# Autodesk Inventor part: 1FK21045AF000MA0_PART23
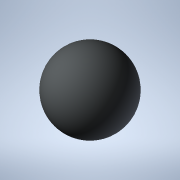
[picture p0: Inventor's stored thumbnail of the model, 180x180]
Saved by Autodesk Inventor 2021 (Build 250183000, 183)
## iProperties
Created: 2025-04
Part Number: 1FK21045AF000MA0_PART23
Material: Generic
Catalog Web Link: www.3dfindit.com
Description: -Servo synchronous motor
Document SubType Name: Modeling
Designer: psAdmin
Mass: 0.137258 g
Surface Area: 1.2868 cm^2
Volume: 0.137258 cm^3
Density: 1 g/cm^3
Appearance: PSOLRGB-212-217-219
Category: PARTsolutions
Title: 1FK21045AF000MA0_PART23
Author: Cadenas PARTsolutions
Comments: Servo synchronous motor
Sending System: PARTsolutions
Preprocessor: ST-DEVELOPER v19.3
PSOL_IDENT_0: {$CADENAS_DATA/23d-libs/siemens_ag/_cat_/8b/0a/1fk21045af000ma0.prj},216 {VTYP=3D},{NB=1FK21045AF000
PSOL_IDENT_1: MA0_PART23},{LINA=1FK21045AF000MA0_PART23},{NN=1FK21045AF000MA0_PART23},{NOPRJ=TRUE},{DATE=19.08.202
PSOL_IDENT_2: 5 14:00:48},{GEOMDATE=30.07.2025 02:00:28},{VERSION=},{LINEID=10},{WBVAR=},{WBNUMERIC=}  {NB=1FK2104
PSOL_IDENT_3: 5AF000MA0_PART23},{LINA=1FK21045AF000MA0_PART23},{KT=DUMMY},{PREVIEW=../../../_pool_/a9/69/p_d211_xx
PSOL_IDENT_4: _00818j.png},{DESCSHORT=SIMOTICS S-1FK2 HD, SINAMICS S210 3AC 400V-480V, 2.4 Nm, 3000 rpm},{DESCLONG=
PSOL_IDENT_5: SIMOTICS S-1FK2 HD servo motor M0=2.4 Nm; PN = 0.75 kW at nN=3000 rpm (380-480 V); PN = 0.375 kW at
PSOL_IDENT_6: nN=1500 rpm (200-240 V); degree of protection IP64; cylindrical shaft D19x40mm; absolute encoder 22-
PSOL_IDENT_7: bit + 12-bit multiturn (encoder AM22DQC); with OCC interface; plug size M17, rotatable; SIMOTICS S-1
PSOL_IDENT_8: FK2 servomotorfor a wide range of uses in industrial environments. SIMOTICS S‑1FK2 servomotors are c
PSOL_IDENT_9: ompact synchronous motors with a high dynamic performance that set themselves apart as a result of t
PSOL_IDENT_10: heir high power density, degree of protection and overload capability. The motors are available in t
PSOL_IDENT_11: wo variants: as High Dynamic variant (highest dynamic performance as a result of the low intrinsic m
PSOL_IDENT_12: oment of inertia for applications demanding a high dynamic performance with low moved masses) - and
PSOL_IDENT_13: as Compact variant (precise and stable closed-loop control for medium up to large moved masses as a
PSOL_IDENT_14: result of a medium intrinsic moment of inertia). SIMOTICSS‑1FK2 servomotors fully exploit their stre
PSOL_IDENT_15: ngths in a system with the SINAMICSS210 frequency converter and simple connection using the one cabl
PSOL_IDENT_16: e connection (OCC). Advantages include the short control and positioning times, fast and precise cor
PSOL_IDENT_17: rection of disturbing quantities as well as stable control with a high dynamic performance. The serv
PSOL_IDENT_18: o motors can be configured to address a wide range of requirements. For example with and without hol
PSOL_IDENT_19: ding brake, IP64 or IP65 degree of protection, singleturn or multiturn absolute encoders - to name j
PSOL_IDENT_20: ust a few. Further, the servomotors are available in different shaft heights extending from 20 to 10
PSOL_IDENT_21: 0. A shaft sealing ring is available to achieve an IP65 degree of protection and for subsequent moun
PSOL_IDENT_22: ting at the motor or as spare part. SIMOTICS - the optimum motor for each and every motion control a
PSOL_IDENT_23: pplication.},{INTNO=195125050112},{SUPPLIERALTNO=1FK2104-5AF00-0MA0},{MANUID=1FK21045AF000MA0},{MANU
PSOL_IDENT_24: NAME=Siemens},{MANUTYPEDESC=Synchronous motor 1FK2-HD 2.4 NM},{AAU732=SIMOTICS},{AAO057=S-1FK2},{AAU
PSOL_IDENT_25: 734=SIMOTICS S-1FK2 HD servo motor M0=2.4 Nm; PN = 0.75 kW at nN=3000 rpm (380-480 V); PN = 0.375 kW
PSOL_IDENT_26: at nN=1500 rpm (200-240 V); degree of protection IP64; cylindrical shaft D19x40mm; absolute encoder
PSOL_IDENT_27: 22-bit + 12-bit multiturn (encoder AM22DQC); with OCC interface; plug size M17, rotatable;},{AAW338=
PSOL_IDENT_28: Synchronous motor 1FK2-HD 2.4 NM},{AAO742=SIMOTICS},{AAO663=4042948692912},{NOCUPEROU=1},{PRICEQUANT
PSOL_IDENT_29: ITY=1},{QUANTITYMIN=1},{QUANTITYINT=1},{CTN=85015100},{COO=DE},{AAO676=1FK2104-5AF00-0MA0},{AAO677=S
PSOL_IDENT_30: iemens AG},{ORDERUNIT=C62},{CONTENTUNIT=C62}
NB: 1FK21045AF000MA0_PART23
NT: Servo synchronous motor
NBSYN: $MANUID._PART23
LINA: 1FK21045AF000MA0_PART23
CATALOG: SIEMENS
PREVIEW: ../../../_pool_/a9/69/p_d211_xx_00818j.png
DESCSHORT: SIMOTICS S-1FK2 HD, SINAMICS S210 3AC 400V-480V, 2.4 Nm, 3000 rpm
DESCLONG: SIMOTICS S-1FK2 HD servo motor M0=2.4 Nm; PN = 0.75 kW at nN=3000 rpm (380-480 V); PN = 0.375 kW at nN=1500 rpm (200-240 V); degree of protection IP64; cylindri
INTNO: 195125050112
SUPPLIERALTNO: 1FK2104-5AF00-0MA0
MANUID: 1FK21045AF000MA0
MANUNAME: Siemens
MANUTYPEDESC: Synchronous motor 1FK2-HD 2.4 NM
AAU732: SIMOTICS
AAO057: S-1FK2
AAU734: SIMOTICS S-1FK2 HD servo motor M0=2.4 Nm; PN = 0.75 kW at nN=3000 rpm (380-480 V); PN = 0.375 kW at nN=1500 rpm (200-240 V); degree of protection IP64; cylindri
AAW338: Synchronous motor 1FK2-HD 2.4 NM
AAO742: SIMOTICS
AAO663: 4042948692912.0
NOCUPEROU: 1
PRICEQUANTITY: 1
QUANTITYMIN: 1
QUANTITYINT: 1
CTN: 85015100
COO: DE
ARTICLENO: 1FK21045AF000MA0_PART23
BOMINFO: 1FK21045AF000MA0_PART23
CREATOR: CADENAS GmbH
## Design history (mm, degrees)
feature "2025_04_17_15_40_42_0766"
body "Solid1"
